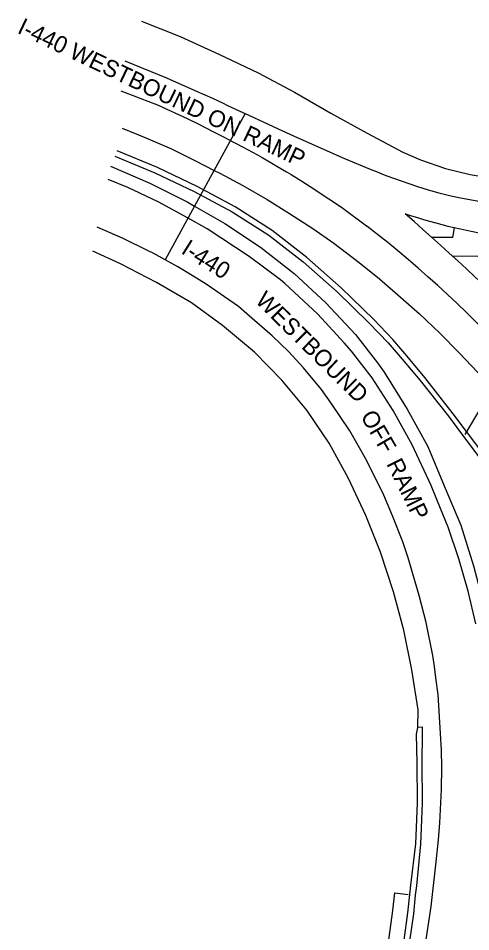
# Model space of a CAD drawing. Extents: x 1730210 to 1732101, y 650763 to 653427.
# Drawn here: x 1730209.8 to 1730371.6, y 652788.8 to 653115.1 of the extents above; entities that cross this region are included whole.
import ezdxf

# ---------------------------------------------------------------- set-up
doc = ezdxf.new("R2010")
doc.units = 0
for name, color, linetype in [('DESIGN - TRAFFIC CONTROL PERMANENT - Pavement Marking', 7, 'Continuous'), ('DESIGN - TRANSPORTATION - Intersection Lines', 7, 'Continuous'), ('DESIGN - TRANSPORTATION - Text', 7, 'Continuous'), ('FUNCTIONAL - TRANSPORTATION - Pavement Marking and Traffic Control', 7, 'Continuous'), ('SURVEY - ROADSIDE BARRIERS with Text', 7, 'Continuous'), ('SURVEY - TRANSPORTATION - Features', 7, 'Continuous'), ('SURVEY - TRANSPORTATION - Roads', 7, 'Continuous'), ('SURVEY - TRANSPORTATION - Roads Text', 7, 'Continuous')]:
    doc.layers.add(name, color=color, linetype=linetype)

msp = doc.modelspace()

# ---------------------------------------------------------------- linework, layer by layer
at = {"layer": 'DESIGN - TRAFFIC CONTROL PERMANENT - Pavement Marking'}
for p, q in [((1730365.19, 653036.83), (1730365.8, 653040.33)), ((1730365.19, 653036.83), (1730357.65, 653036.87)), ((1730374.16, 653030.08), (1730365.08, 653030.13))]:
    msp.add_line(p, q, dxfattribs=at)
for points in [[(1730246.52, 653089.18), (1730257.72, 653084.91), (1730259.59, 653084.19), (1730261.4, 653083.36), (1730268.66, 653080.01), (1730270.47, 653079.18), (1730274.09, 653077.48), (1730279.4, 653074.71), (1730282.94, 653072.87), (1730284.72, 653071.94), (1730290.03, 653069.17), (1730293.57, 653067.32), (1730295.34, 653066.4), (1730297.06, 653065.38), (1730300.5, 653063.35), (1730302.22, 653062.33), (1730305.66, 653060.3), (1730307.38, 653059.28), (1730310.78, 653057.19), (1730312.45, 653056.09), (1730315.8, 653053.91), (1730319.14, 653051.72), (1730320.81, 653050.63), (1730322.49, 653049.54), (1730325.83, 653047.35), (1730333.81, 653041.34), (1730334.47, 653040.85)], [(1730290.97, 653081.06), (1730299.1, 653077.27), (1730302.73, 653075.58), (1730308.2, 653073.15), (1730319.15, 653068.28), (1730326.44, 653065.04), (1730335.66, 653061.22), (1730337.5, 653060.46), (1730341.21, 653059), (1730352.51, 653055.04), (1730354.42, 653054.46), (1730356.33, 653053.88), (1730360.15, 653052.77), (1730362.09, 653052.3), (1730364.03, 653051.83), (1730367.92, 653050.97), (1730369.89, 653050.6), (1730375.78, 653049.62)], [(1730279.88, 653060.81), (1730281.86, 653059.79), (1730290.11, 653055.41), (1730298.77, 653050.43), (1730306.79, 653045.43), (1730315.16, 653039.98), (1730322.67, 653034.75), (1730331.63, 653027.94), (1730338.9, 653022.07), (1730346.44, 653015.53), (1730353.22, 653009.5), (1730360.49, 653002.64), (1730367.3, 652995.75), (1730374.2, 652988.52), (1730385.19, 652976.62)], [(1730373.37, 652898.83), (1730370.67, 652910.52), (1730367.31, 652922.04), (1730363.47, 652933.41), (1730359.71, 652942.68), (1730357.45, 652948.24), (1730350.64, 652962.71), (1730343.87, 652974.97), (1730336.3, 652986.74), (1730328.98, 652996.25), (1730326.33, 652999.24), (1730318.2, 653008.06), (1730316.84, 653009.53), (1730305.08, 653020.36), (1730303.56, 653021.66), (1730292.39, 653030.09), (1730277.34, 653039.93), (1730270.5, 653043.67)], [(1730355.62, 652786.04), (1730356.22, 652789.99), (1730357.43, 652797.89), (1730359.23, 652813.78), (1730360.02, 652821.73), (1730360.54, 652827.71), (1730361.15, 652839.69), (1730361.22, 652847.68), (1730361.06, 652853.68), (1730360.81, 652859.67), (1730359.88, 652873.64), (1730359.11, 652879.59), (1730358.57, 652883.56), (1730358.04, 652887.52), (1730355.63, 652899.28), (1730353.16, 652908.96), (1730349.14, 652922.38), (1730347.32, 652928.09), (1730343.64, 652937.39), (1730340.49, 652944.74), (1730334.36, 652957.33), (1730328.34, 652967.71), (1730321.65, 652977.66), (1730318.21, 652982.58), (1730311.77, 652990.22), (1730306.4, 652996.15), (1730300.61, 653001.66), (1730291.56, 653009.53), (1730288.54, 653012.14), (1730277.03, 653020.1), (1730271.94, 653023.27), (1730266.81, 653026.37), (1730262.36, 653028.81)]]:
    msp.add_lwpolyline(points, dxfattribs=at)
for centre, radius, start, end in [((1730406.08, 653215.77), 180.01, 251.24, 262.7955), ((1729392.41, 651966.14), 1441.58, 43.127, 48.47054), ((1730082.94, 652714.55), 412, 31.4096, 52.3723)]:
    msp.add_arc(centre, radius, start, end, dxfattribs=at)
at = {"layer": 'DESIGN - TRANSPORTATION - Intersection Lines'}
msp.add_line((1730290.97, 653081.06), (1730262.36, 653028.81), dxfattribs=at)
at = {"layer": 'DESIGN - TRANSPORTATION - Text'}
msp.add_line((1730369.55, 652966.4), (1730389.5, 653000.4), dxfattribs=at)
at = {"layer": 'FUNCTIONAL - TRANSPORTATION - Pavement Marking and Traffic Control'}
msp.add_arc((1729392.41, 651966.14), 1441.58, 43.127, 48.47054, dxfattribs=at)
at = {"layer": 'SURVEY - ROADSIDE BARRIERS with Text'}
for points in [[(1730377.65, 652957.37), (1730370.05, 652967.58), (1730365.29, 652973.88), (1730355.2, 652986.83), (1730348.75, 652994.6), (1730343.7, 653000.38), (1730336.88, 653007.54), (1730325.24, 653018.88), (1730312.96, 653029.7), (1730300.57, 653039.33), (1730287.37, 653047.78), (1730273.76, 653055.04), (1730259.59, 653061.77), (1730245.17, 653067.81)], [(1730244.35, 653065.91), (1730258.67, 653059.93), (1730272.72, 653053.24), (1730286.26, 653046.01), (1730299.37, 653037.63), (1730311.67, 653028.09), (1730323.76, 653017.4), (1730335.29, 653006.23), (1730342, 652999.15), (1730347.05, 652993.36), (1730353.48, 652985.73), (1730363.57, 652972.96), (1730368.32, 652966.74), (1730375.88, 652956.6), (1730377.65, 652957.37)]]:
    msp.add_lwpolyline(points, dxfattribs=at)
at = {"layer": 'SURVEY - TRANSPORTATION - Features'}
for points in [[(1730253.82, 653114.13), (1730267.75, 653108.61), (1730281.81, 653102.2), (1730295.59, 653095.65), (1730308.55, 653088.68), (1730321.61, 653081.2), (1730334.49, 653074.04), (1730347.31, 653067.34), (1730353.58, 653064.62), (1730362.5, 653061.44), (1730371.34, 653059.29), (1730380.86, 653057.75), (1730389.87, 653056.86), (1730399.5, 653056.72), (1730408.84, 653057.42), (1730417.67, 653058.69), (1730426.73, 653060.57), (1730435.96, 653063.41), (1730444.1, 653066.73), (1730450.28, 653069.61)], [(1730242.84, 653062.34), (1730256.85, 653056.28), (1730270.49, 653049.39), (1730272.87, 653048.01)], [(1730272.87, 653048.01), (1730283.61, 653041.79), (1730296.37, 653033.41), (1730308.39, 653023.98), (1730319.79, 653013.43), (1730330.32, 653002.12), (1730338.26, 652992.05), (1730340.57, 652988.7), (1730348.86, 652975.48), (1730356.23, 652962.2), (1730362.05, 652948.14), (1730367.97, 652934.08), (1730372.53, 652919.59), (1730376.43, 652904.68), (1730379.45, 652889.74), (1730380.84, 652874.59), (1730381.75, 652866.73)], [(1730347.71, 652785.85), (1730349.04, 652795.59), (1730349.79, 652802.13), (1730350.2, 652805.52), (1730351.91, 652820.29), (1730352.55, 652834.89), (1730352.42, 652849.23), (1730352.17, 652859.39), (1730352.6, 652861.75), (1730352.77, 652868.11), (1730350.46, 652882.38), (1730347.64, 652896.54), (1730343.94, 652910.3), (1730339.31, 652924.42), (1730334.05, 652937.55), (1730327.89, 652950.76), (1730321.01, 652963.38), (1730313.01, 652975.18), (1730304.08, 652985.84), (1730294.3, 652995.83), (1730282.82, 653005.43), (1730271.78, 653013.44), (1730259.26, 653020.77), (1730246.31, 653027.45), (1730236.49, 653031.99)], [(1730337.98, 652729.24), (1730342.02, 652745.63), (1730345.43, 652760.21), (1730347.56, 652770.69), (1730349.84, 652785.47), (1730351.17, 652795.26), (1730351.85, 652801.9), (1730352.26, 652805.29), (1730353.73, 652820.11), (1730354.38, 652834.8), (1730354.26, 652849.28), (1730354.32, 652859.54), (1730354.37, 652861.87), (1730352.6, 652861.75)], [(1730323.87, 652705.55), (1730326.04, 652713.45), (1730327.06, 652716.97), (1730330.81, 652731.15), (1730334.78, 652747.28), (1730338.17, 652761.86), (1730340.23, 652772.01), (1730342.4, 652786.78), (1730343.71, 652796.4), (1730344.43, 652802.74), (1730349.2, 652802.2)]]:
    msp.add_lwpolyline(points, dxfattribs=at)
at = {"layer": 'SURVEY - TRANSPORTATION - Roads'}
for points in [[(1730247.97, 653099.92), (1730262.75, 653093.83), (1730273.73, 653089.02), (1730279.2, 653086.58), (1730281.01, 653085.73), (1730282.81, 653084.88), (1730284.62, 653084.03), (1730290.05, 653081.49), (1730290.97, 653081.06)], [(1730246.92, 653075.92), (1730255.39, 653072.47), (1730264.55, 653068.48), (1730272.97, 653064.35), (1730279.88, 653060.81)], [(1730270.5, 653043.67), (1730259.81, 653049.53), (1730248.98, 653054.65), (1730241.94, 653057.58)], [(1730262.36, 653028.81), (1730258.05, 653031.17), (1730256.28, 653032.09), (1730247.29, 653036.46), (1730238.08, 653040.53)]]:
    msp.add_lwpolyline(points, dxfattribs=at)

# ---------------------------------------------------------------- texts
at = {"layer": 'SURVEY - TRANSPORTATION - Roads Text'}
for s, rotation, p in [('I-440 WESTBOUND ON RAMP', 334.5557, (1730209.14, 653110.03)), ('I-440', 327.7383, (1730267.67, 653031.38)), ('WESTBOUND', 315.362, (1730294.22, 653013.89)), ('OFF', 300.0863, (1730332.01, 652972.98)), ('RAMP', 296.1726, (1730341.31, 652956.03))]:
    msp.add_text(s, height=6, rotation=rotation, dxfattribs=at).set_placement(p)

doc.saveas('drawing.dxf')
